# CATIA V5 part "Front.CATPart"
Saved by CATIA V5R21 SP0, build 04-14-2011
Part number: Front
Bounding box of the stored display mesh (mm): x 0 to 2.8, y -92.8 to 92.8, z -5 to 60
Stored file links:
  C:\Users\Pouria\Desktop\Box\Front.CATPart
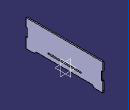
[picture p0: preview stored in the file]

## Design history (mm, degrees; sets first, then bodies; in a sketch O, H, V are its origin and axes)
Body1 (main body)
  Sketch1 on yz-plane, origin (0, 0, 0), H (0, 1, 0), V (0, 0, 1)
    point P1 (-92.8, 0)
    line L1 (-67.8, 0) -> (67.8, 0)
    line L2 (92.8, 0) -> (92.8, 20)
    line L3 (92.8, 60) -> (-92.8, 60)
    line L4 (-92.8, 60) -> (-92.8, 40)
    point P2 (92.8, 0)
    point P3 (92.8, 60)
    point P5 (92.8, 40)
    line L5 (92.8, 40) -> (90, 40)
    line L6 (90, 40) -> (90, 20)
    line L7 (90, 20) -> (92.8, 20)
    line L8 (-92.8, 40) -> (-90, 40)
    line L9 (-90, 40) -> (-90, 20)
    line L10 (-90, 20) -> (-92.8, 20)
    point P12 (-92.8, 20)
    line L11 (67.8, 0) -> (72.8, -5)
    line L12 (72.8, -5) -> (92.8, -5)
    point P15 (92.8, -5)
    line L13 (92.8, -5) -> (92.8, 0)
    line L14 (-92.8, 0) -> (-92.8, -5)
    line L15 (-92.8, -5) -> (-72.8, -5)
    line L16 (-72.8, -5) -> (-67.8, 0)
    line L17 (92.8, 40) -> (92.8, 60)
    line L18 (-92.8, 20) -> (-92.8, 0)
    point P19 (0, 11.4)
    line L19 (40, 12.8) -> (40, 10)
    line L20 (40, 10) -> (-40, 10)
    line L21 (-40, 10) -> (-40, 12.8)
    line L22 (-40, 12.8) -> (40, 12.8)
    length L3 = 185.6
    length L6 = 20
    length L9 = 20
    length L5 = 2.8
    length L8 = 2.8
    distance L7 L1 = 20
    distance L10 L1 = 20
    length L12 = 20
    length L13 = 5
    length L15 = 20
    length L14 = 5
    angle L11 L1 = 45
    angle L16 L1 = 45
    distance P2 P3 = 60
    distance L20 L1 = 10
    length L19 = 2.8
    length L22 = 80
    coincidence: P1 H, P5 L2, P12 L4, P15 L2, L1 H, P2 H, L2 L17, L4 L18, P19 V
    horizontal: L1 H, L3 H, L5 H, L7 H, L8 H, L10 H, L12 H, L15 H, L20 H, L22 H
    vertical: L2 V, L4 V, L6 V, L9 V, L13 V, L14 V, L17 V, L18 V, L19 V, L21 V
    symmetry: L2 L4 V
    equidistance: L19 L21 P19, L20 L22 P19
  Pad1: profile Sketch1, direction (1, 0, 0), length 2.8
